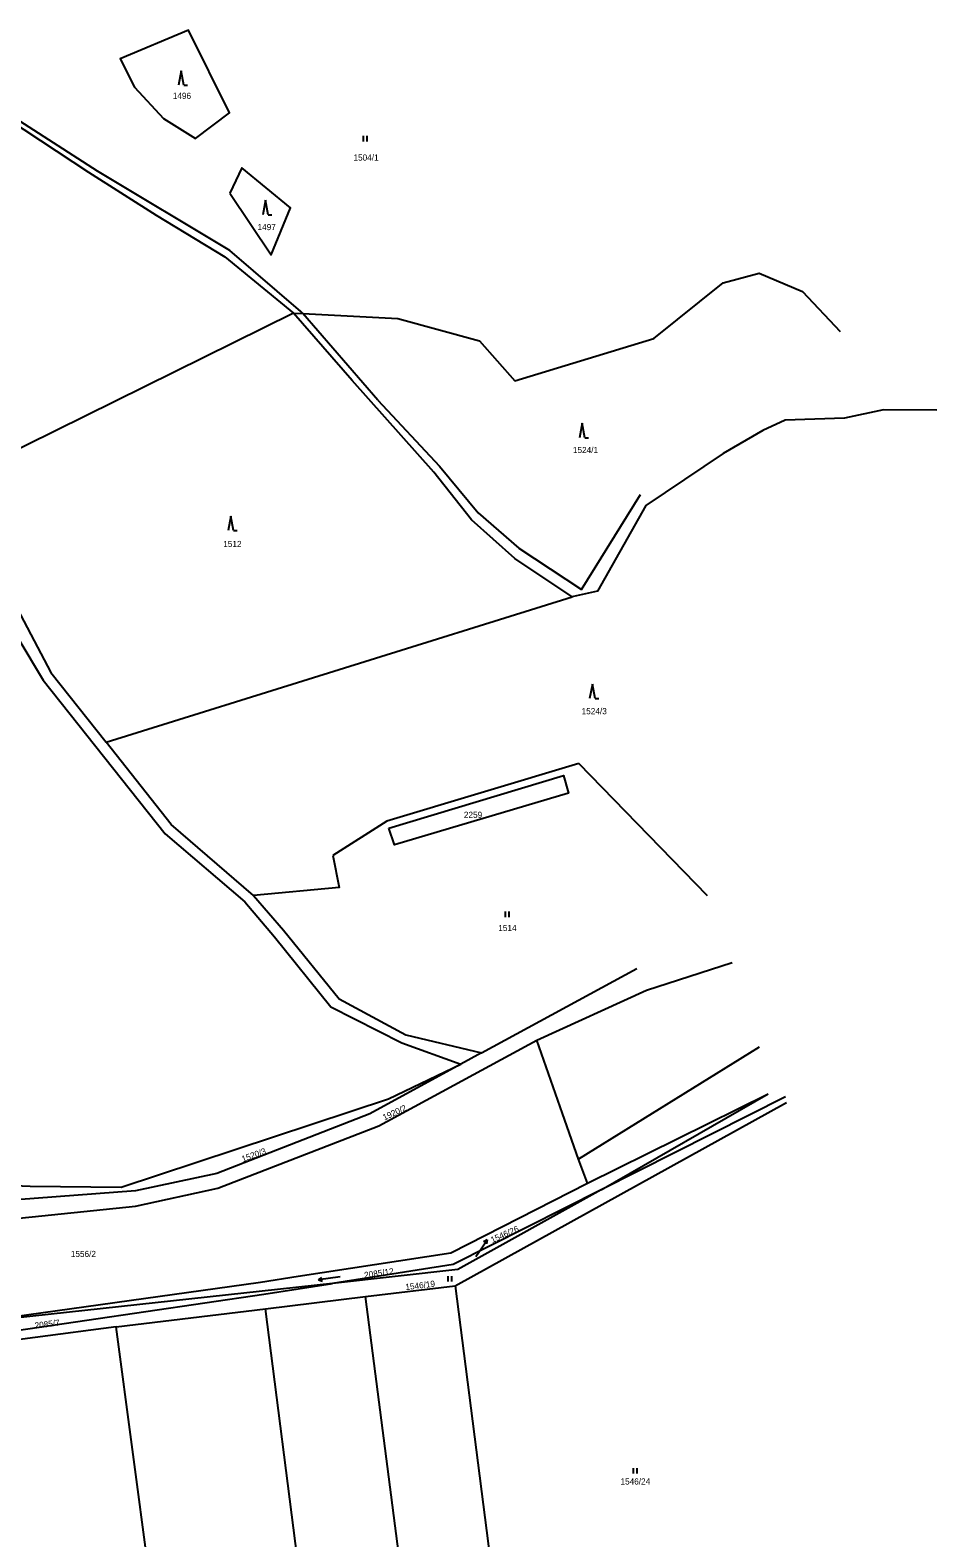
# Model space of a CAD drawing. Extents: x -793666 to -785424, y -1118958 to -1108761.
# Drawn here: x -792390.5 to -792140, y -1111162.3 to -1110745.5 of the extents above; entities that cross this region are included whole.
import ezdxf

# ---------------------------------------------------------------- set-up
doc = ezdxf.new("R2010")
doc.units = 0
for name, color, linetype in [('Hranice parcel', 7, 'Continuous'), ('Parcelní čísla', 7, 'Continuous'), ('Pop  PČ popisy', 7, 'Continuous'), ('Vnitřní kresba', 7, 'Continuous'), ('Značky kultur', 7, 'Continuous')]:
    doc.layers.add(name, color=color, linetype=linetype)

msp = doc.modelspace()

# ---------------------------------------------------------------- linework, layer by layer
at = {"layer": 'Hranice parcel'}
for p, q in [((-792317.68, -1110823.69), (-792403.33, -1110866.05)), ((-792369.49, -1110942.36), (-792240.75, -1110902.15)), ((-792203.34, -1110984.82), (-792238.88, -1110948.19)), ((-792265.74, -1111028.23), (-792222.8, -1111004.85)), ((-792286.67, -1111023.19), (-792265.74, -1111028.23)), ((-792287.76, -1111025.49), (-792271.45, -1111031.34)), ((-792265.74, -1111028.23), (-792271.45, -1111031.34)), ((-792236.46, -1111064.25), (-792186.55, -1111039.58)), ((-792232.66, -1111066.04), (-792186.55, -1111039.58)), ((-792181.74, -1111040.37), (-792232.66, -1111066.04)), ((-792273, -1111092.58), (-792181.52, -1111041.95)), ((-792236.46, -1111064.25), (-792238.97, -1111057.62)), ((-792306.91, -1111091.93), (-792407.39, -1111102.88)), ((-792297.81, -1111095.6), (-792273, -1111092.58)), ((-792273, -1111092.58), (-792252.78, -1111251.91)), ((-792325.44, -1111098.96), (-792297.81, -1111095.6)), ((-792273.22, -1111285.03), (-792297.81, -1111095.6)), ((-792366.71, -1111103.99), (-792325.44, -1111098.96)), ((-792296.91, -1111323.44), (-792325.44, -1111098.96)), ((-792330.42, -1111377.77), (-792366.71, -1111103.99))]:
    msp.add_line(p, q, dxfattribs=at)
for points in [[(-792344.83, -1110775.42), (-792335.39, -1110768.36), (-792346.77, -1110745.5), (-792365.59, -1110753.46), (-792361.69, -1110761.3), (-792353.66, -1110769.94), (-792344.83, -1110775.42)], [(-792335.28, -1110790.59), (-792323.93, -1110807.57), (-792318.54, -1110794.62), (-792332.01, -1110783.56), (-792335.28, -1110790.59)], [(-792317.68, -1110823.69), (-792315.15, -1110823.83), (-792288.9, -1110825.23), (-792266.34, -1110831.42), (-792256.52, -1110842.45), (-792218.19, -1110830.78), (-792199.01, -1110815.38), (-792189.05, -1110812.67), (-792177.1, -1110817.79), (-792166.62, -1110828.82)], [(-792240.75, -1110902.15), (-792256.52, -1110891.54), (-792268.57, -1110880.91), (-792278.9, -1110867.73), (-792301.47, -1110842.31), (-792317.68, -1110823.69)], [(-792139.95, -1110850.55), (-792154.68, -1110850.49), (-792165.48, -1110852.75), (-792181.87, -1110853.3), (-792188.06, -1110856.17), (-792198.98, -1110862.49), (-792220.39, -1110876.87), (-792233.74, -1110900.55), (-792240.35, -1110902.03), (-792240.75, -1110902.15)], [(-792403.33, -1110866.05), (-792404.22, -1110878.24), (-792396.84, -1110900.08), (-792384.75, -1110923.07), (-792369.49, -1110942.36)], [(-792401.29, -1110901.3), (-792386.84, -1110925.19), (-792353.2, -1110967.68), (-792331.14, -1110986.51), (-792322.99, -1110996.18), (-792307.4, -1111015.46), (-792287.76, -1111025.49)], [(-792328.81, -1110984.69), (-792351.51, -1110965.1), (-792369.49, -1110942.36)], [(-792238.88, -1110948.19), (-792291.96, -1110964.14), (-792306.85, -1110973.64)], [(-792291.39, -1110966.06), (-792243.11, -1110951.56), (-792241.72, -1110956.4), (-792289.79, -1110970.74), (-792291.39, -1110966.06)], [(-792306.85, -1110973.64), (-792305.09, -1110982.49), (-792328.81, -1110984.69)], [(-792328.81, -1110984.69), (-792320.46, -1110994.34), (-792305.1, -1111013.27), (-792286.67, -1111023.19)], [(-792250.44, -1111024.74), (-792220.19, -1111010.84), (-792196.48, -1111003.27)], [(-792523.64, -1111100.49), (-792407.92, -1111075.39), (-792361.39, -1111070.62), (-792338.58, -1111065.63), (-792294.17, -1111048.39), (-792250.44, -1111024.74)], [(-792238.97, -1111057.62), (-792243.39, -1111044.94), (-792250.44, -1111024.74)], [(-792189.03, -1111026.62), (-792191.73, -1111028.29), (-792238.97, -1111057.62)], [(-792463.74, -1111037.04), (-792425.08, -1111055.31), (-792403.75, -1111064.5), (-792390.47, -1111065.03), (-792365.3, -1111065.34), (-792291.42, -1111040.89), (-792271.45, -1111031.34)], [(-792271.45, -1111031.34), (-792296.66, -1111045.04), (-792338.86, -1111061.54), (-792361.36, -1111066.36), (-792394.27, -1111068.8)], [(-792407.39, -1111102.88), (-792326.81, -1111091.56), (-792316.4, -1111089.97), (-792274.21, -1111083.5), (-792236.46, -1111064.25)], [(-792232.66, -1111066.04), (-792272.28, -1111088.1), (-792306.91, -1111091.93)], [(-792232.66, -1111066.04), (-792273.61, -1111086.69), (-792306.91, -1111091.93)], [(-792525.02, -1111143.72), (-792518.75, -1111141.25), (-792515.51, -1111140.14), (-792435.87, -1111112.41), (-792407.53, -1111106.87), (-792325.89, -1111094.91), (-792306.91, -1111091.93)], [(-792366.71, -1111103.99), (-792433.98, -1111112.84), (-792515.99, -1111144), (-792517.15, -1111145.92)]]:
    msp.add_lwpolyline(points, dxfattribs=at)
at = {"layer": 'Pop  PČ popisy'}
for p, q in [((-792265.89, -1111082.42), (-792264.21, -1111079.93)), ((-792264.21, -1111079.93), (-792265.19, -1111080.48)), ((-792264.21, -1111079.93), (-792264.36, -1111081.04)), ((-792267.29, -1111084.49), (-792265.89, -1111082.42))]:
    msp.add_line(p, q, dxfattribs=at)
at = {"layer": 'Vnitřní kresba'}
for p, q in [((-792371.88, -1110784.48), (-792396.23, -1110768.85)), ((-792396.51, -1110770.15), (-792374.4, -1110784.73)), ((-792374.4, -1110784.73), (-792355.62, -1110796.65)), ((-792335.29, -1110806.37), (-792371.88, -1110784.48)), ((-792355.62, -1110796.65), (-792336.66, -1110808.17)), ((-792315.66, -1110823.24), (-792335.29, -1110806.37)), ((-792336.66, -1110808.17), (-792317.68, -1110823.69)), ((-792315.15, -1110823.83), (-792315.66, -1110823.24)), ((-792294.37, -1110847.83), (-792315.15, -1110823.83)), ((-792294.37, -1110847.83), (-792277.38, -1110866.03)), ((-792277.38, -1110866.03), (-792266.66, -1110878.95)), ((-792238.1, -1110900.12), (-792221.84, -1110873.87)), ((-792266.66, -1110878.95), (-792255.43, -1110888.73)), ((-792255.43, -1110888.73), (-792238.1, -1110900.12))]:
    msp.add_line(p, q, dxfattribs=at)
at = {"layer": 'Značky kultur'}
for p, q in [((-792348.72, -1110756.7), (-792349.47, -1110760.7)), ((-792347.97, -1110760.7), (-792348.72, -1110756.7)), ((-792347.97, -1110760.7), (-792346.97, -1110760.7)), ((-792298.34, -1110776.24), (-792298.34, -1110774.74)), ((-792297.34, -1110776.24), (-792297.34, -1110774.74)), ((-792325.44, -1110792.52), (-792326.19, -1110796.52)), ((-792324.69, -1110796.52), (-792325.44, -1110792.52)), ((-792324.69, -1110796.52), (-792323.69, -1110796.52)), ((-792237.97, -1110854.18), (-792238.72, -1110858.18)), ((-792237.22, -1110858.18), (-792237.97, -1110854.18)), ((-792237.22, -1110858.18), (-792236.22, -1110858.18)), ((-792335.05, -1110879.83), (-792335.8, -1110883.83)), ((-792334.3, -1110883.83), (-792335.05, -1110879.83)), ((-792334.3, -1110883.83), (-792333.3, -1110883.83)), ((-792235.14, -1110926.28), (-792235.89, -1110930.28)), ((-792234.39, -1110930.28), (-792235.14, -1110926.28)), ((-792234.39, -1110930.28), (-792233.39, -1110930.28)), ((-792259.15, -1110990.66), (-792259.15, -1110989.16)), ((-792258.15, -1110990.66), (-792258.15, -1110989.16)), ((-792304.84, -1111090.1), (-792310.78, -1111090.93)), ((-792310.78, -1111090.93), (-792309.88, -1111090.3)), ((-792274.94, -1111091.46), (-792274.94, -1111089.96)), ((-792273.94, -1111091.46), (-792273.94, -1111089.96)), ((-792310.78, -1111090.93), (-792309.74, -1111091.29)), ((-792223.73, -1111144.5), (-792223.73, -1111143)), ((-792222.73, -1111144.5), (-792222.73, -1111143))]:
    msp.add_line(p, q, dxfattribs=at)

# ---------------------------------------------------------------- texts
at = {"layer": 'Parcelní čísla'}
for s, p in [('1496', (-792351.07, -1110764.5)), ('1504/1', (-792301.14, -1110781.57)), ('1497', (-792327.65, -1110800.78)), ('1524/1', (-792240.51, -1110862.41)), ('1512', (-792337.13, -1110888.39)), ('1524/3', (-792238.1, -1110934.61)), ('2259', (-792270.63, -1110963.25)), ('1514', (-792261.13, -1110994.55)), ('1556/2', (-792379.25, -1111084.65)), ('1546/24', (-792227.36, -1111147.55))]:
    msp.add_text(s, height=1.7, dxfattribs=at).set_placement(p)
for s, rotation, p in [('1920/2', 25, (-792292.58, -1111046.95)), ('1520/3', 20, (-792331.68, -1111058.43)), ('1546/26', 24, (-792262.77, -1111080.81)), ('2085/12', 8, (-792298.06, -1111090.52)), ('1546/19', 7, (-792286.68, -1111093.83)), ('2085/7', 7, (-792389.13, -1111104.46))]:
    msp.add_text(s, height=1.7, rotation=rotation, dxfattribs=at).set_placement(p)

doc.saveas('drawing.dxf')
